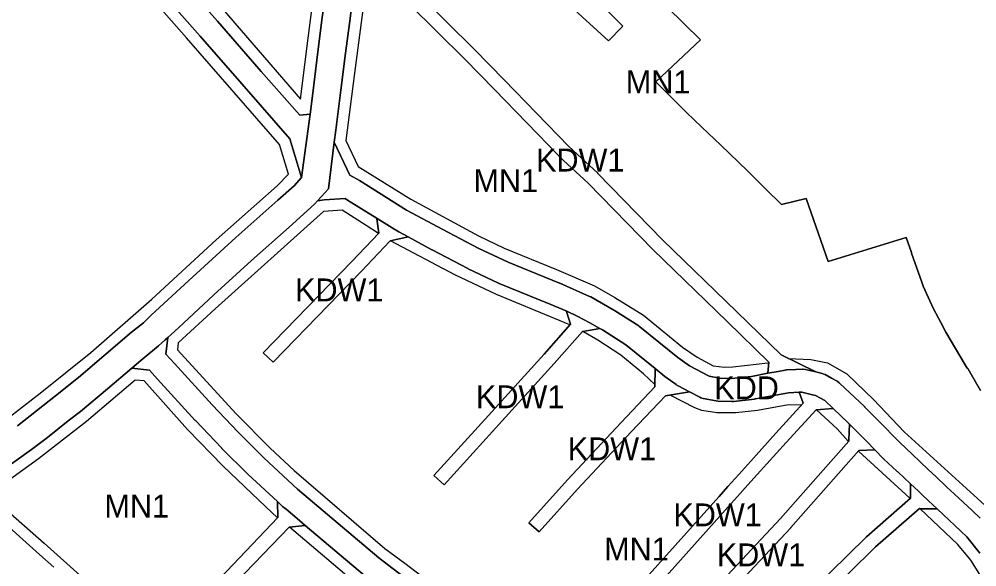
# Model space of a CAD drawing. Extents: x -284239 to -281592, y 34477 to 37267.
# Drawn here: x -283512.6 to -283094, y 35490.3 to 35729.6 of the extents above; entities that cross this region are included whole.
import ezdxf

# ---------------------------------------------------------------- set-up
doc = ezdxf.new("R2010")
doc.units = 0
for name, color, linetype in [('linie_rozgraniczajace', 7, 'Continuous'), ('linie_zabudowy_nieprzekraczalne', 7, 'Continuous'), ('oznaczenia_przeznaczen', 7, 'Continuous')]:
    doc.layers.add(name, color=color, linetype=linetype)

msp = doc.modelspace()

# ---------------------------------------------------------------- linework, layer by layer
at = {"layer": 'linie_rozgraniczajace'}
for points in [[(-283349.735, 35805.983), (-283349.502, 35806.716), (-283347.736, 35812.259), (-283345.668, 35818.639), (-283344.649, 35821.859), (-283344.561, 35822.155), (-283342.259, 35814.684), (-283340.653, 35813.099), (-283314.405, 35787.199), (-283293.67, 35766.75), (-283260.03, 35733.57), (-283258.538, 35733.588), (-283255.81, 35733.62), (-283248.69, 35726.59), (-283255.01, 35720.19), (-283271.48, 35735.12), (-283286.84, 35750.42), (-283304.28, 35767.69), (-283309.22, 35772.58), (-283343.987, 35807.004), (-283344.662, 35807.672)], [(-283405.892, 35583.865), (-283367.249, 35623.692), (-283355.369, 35636.167), (-283356.246, 35642.43), (-283356.174, 35642.531), (-283351.873, 35639.838), (-283348.414, 35637.671), (-283348.223, 35637.573), (-283348.144, 35637.513), (-283346.6, 35636.675), (-283342.497, 35634.45), (-283349.694, 35632.864), (-283350.526, 35632.552), (-283362.924, 35619.536), (-283362.94, 35619.513), (-283401.586, 35579.687)], [(-283331.293, 35530.227), (-283305.991, 35558.112), (-283283.18, 35583.183), (-283271.69, 35596.417), (-283273.302, 35601.939), (-283273.289, 35601.964), (-283268.654, 35599.915), (-283263.111, 35596.934), (-283258.791, 35594.465), (-283266.225, 35593.161), (-283266.426, 35593.161), (-283278.699, 35579.197), (-283278.724, 35579.164), (-283301.549, 35554.079), (-283326.849, 35526.195)], [(-283289.83, 35509.614), (-283272.958, 35528.334), (-283272.93, 35528.369), (-283249.481, 35553.42), (-283234.751, 35568.99), (-283234.584, 35576.912), (-283230.431, 35573.556), (-283225.502, 35570.036), (-283225.128, 35569.768), (-283224.555, 35569.415), (-283219.593, 35566.796), (-283230.165, 35565.107), (-283245.112, 35549.31), (-283268.53, 35524.289), (-283285.373, 35505.597)], [(-283261.298, 35460.15), (-283210.762, 35516.507), (-283206.679, 35521.057), (-283202.803, 35525.377), (-283198.107, 35530.61), (-283194.076, 35535.102), (-283181.848, 35548.728), (-283169.95, 35561.785), (-283171.609, 35566.589), (-283170.52, 35566.632), (-283166.417, 35565.662), (-283164.569, 35565.225), (-283162.307, 35563.981), (-283160.442, 35562.955), (-283156.878, 35559.563), (-283164.204, 35558.906), (-283177.398, 35544.705), (-283190.045, 35530.61), (-283194.076, 35526.119), (-283198.618, 35521.057), (-283202.803, 35516.393), (-283206.296, 35512.5), (-283256.831, 35456.145)], [(-283242.392, 35442.939), (-283213.619, 35475.417), (-283213.588, 35475.438), (-283213.562, 35475.479), (-283179.793, 35511.495), (-283161.166, 35532.63), (-283149.95, 35545.248), (-283149.998, 35545.727), (-283149.736, 35552.671), (-283149.639, 35552.65), (-283146.347, 35549.301), (-283144.476, 35547.397), (-283142.132, 35545.012), (-283138.586, 35541.406), (-283145.528, 35541.192), (-283156.673, 35528.655), (-283175.322, 35507.493), (-283175.356, 35507.469), (-283175.384, 35507.425), (-283209.156, 35471.406), (-283237.901, 35438.96)], [(-283221.889, 35418.595), (-283197.68, 35445.979), (-283197.655, 35445.997), (-283197.633, 35446.031), (-283166.082, 35480.096), (-283166.025, 35480.135), (-283165.984, 35480.197), (-283142.436, 35503.348), (-283142.351, 35503.404), (-283142.303, 35503.471), (-283123.015, 35520.27), (-283123.015, 35526.596), (-283119.508, 35523.325), (-283118.003, 35521.92), (-283115.117, 35519.192), (-283111.325, 35515.608), (-283118.634, 35515.726), (-283119.023, 35515.79), (-283138.294, 35499.006), (-283161.727, 35475.967), (-283193.208, 35441.979), (-283217.394, 35414.621)], [(-283459.881, 35455.783), (-283452.711, 35455.963), (-283399.464, 35511.822), (-283399.464, 35511.924), (-283399.734, 35518.856), (-283397.587, 35516.882), (-283397.44, 35516.75), (-283395.961, 35515.497), (-283391.099, 35511.382), (-283387.556, 35508.383), (-283394.625, 35507.71), (-283448.28, 35451.829), (-283448.198, 35444.961), (-283451.752, 35448.213), (-283456.211, 35452.291), (-283456.735, 35452.771)], [(-283448.28, 35451.829), (-283394.625, 35507.71), (-283387.556, 35508.383), (-283361.724, 35486.517), (-283361.651, 35486.472), (-283361.462, 35486.31), (-283335.431, 35466.436), (-283335.282, 35466.336), (-283335.195, 35466.214), (-283319.25, 35452.214), (-283318.647, 35444.882), (-283324.984, 35437.311), (-283356.337, 35432.416), (-283382.95, 35396.045), (-283383.06, 35396.036), (-283389.857, 35395.197), (-283396.132, 35400.193), (-283407.596, 35409.26), (-283420.363, 35420.255), (-283434.537, 35432.552), (-283440.842, 35438.232), (-283448.198, 35444.961)]]:
    msp.add_lwpolyline(points, close=True, dxfattribs=at)
for points in [[(-283445.477, 35750.899), (-283425.955, 35728.745), (-283406.767, 35706.816), (-283389.981, 35687.607), (-283385.372, 35688.169), (-283389.119, 35660.419), (-283394.259, 35677.377), (-283414.295, 35700.233), (-283433.469, 35722.148), (-283452.999, 35744.31)], [(-283377.998, 35745.258), (-283380.239, 35729.365), (-283382.48, 35711.7), (-283384.251, 35697.318), (-283385.372, 35688.169), (-283389.981, 35687.607), (-283406.767, 35706.816), (-283425.955, 35728.745), (-283445.477, 35750.899)], [(-283350.085, 35752.642), (-283313.572, 35716.394), (-283313.552, 35716.37), (-283300.572, 35703.128), (-283272.378, 35674.01), (-283259.737, 35662.291), (-283259.695, 35662.23), (-283259.629, 35662.185), (-283231.396, 35633.234), (-283198.892, 35601.751), (-283179.603, 35582.897), (-283164.461, 35575.475), (-283168.882, 35576.52), (-283170.032, 35576.654), (-283170.133, 35576.634), (-283170.224, 35576.65), (-283173.099, 35576.54), (-283177.104, 35576.386), (-283177.216, 35576.361), (-283177.833, 35576.304), (-283180.86, 35575.736), (-283185.361, 35574.892), (-283184.93, 35579.715), (-283203.076, 35597.451), (-283235.601, 35628.954), (-283235.626, 35628.99), (-283235.662, 35629.014), (-283263.872, 35657.943), (-283276.516, 35669.665), (-283276.562, 35669.731), (-283276.632, 35669.778), (-283304.87, 35698.942), (-283317.814, 35712.15), (-283354.266, 35748.338)], [(-283127.717, 35544.613), (-283137.344, 35554.407), (-283142.918, 35560.078), (-283142.99, 35560.126), (-283143.037, 35560.194), (-283154.017, 35570.646), (-283154.215, 35570.774), (-283155.055, 35571.405), (-283157.487, 35572.743), (-283160.346, 35574.315), (-283160.843, 35574.554), (-283161.606, 35574.8), (-283164.461, 35575.475), (-283179.603, 35582.897), (-283198.892, 35601.751), (-283231.396, 35633.234), (-283259.629, 35662.185), (-283259.695, 35662.23), (-283259.737, 35662.291), (-283272.378, 35674.01), (-283300.572, 35703.128), (-283313.552, 35716.37), (-283313.572, 35716.394), (-283350.085, 35752.642)], [(-283354.266, 35748.338), (-283317.814, 35712.15), (-283304.87, 35698.942), (-283276.632, 35669.778), (-283276.562, 35669.731), (-283276.516, 35669.665), (-283263.872, 35657.943), (-283235.662, 35629.014), (-283235.626, 35628.99), (-283235.601, 35628.954), (-283203.076, 35597.451), (-283184.93, 35579.715), (-283185.361, 35574.892), (-283192.474, 35573.558), (-283201.191, 35572.562), (-283206.465, 35572.736), (-283211.035, 35573.586), (-283219.589, 35578.101), (-283224.748, 35581.786), (-283241.365, 35595.25), (-283241.547, 35595.359), (-283241.825, 35595.581), (-283252.408, 35602.328), (-283252.544, 35602.399), (-283252.615, 35602.453), (-283262.802, 35608.274), (-283263.242, 35608.49), (-283263.273, 35608.512), (-283276.238, 35614.2), (-283276.308, 35614.215), (-283276.369, 35614.256), (-283298.931, 35623.399), (-283311.937, 35629.512), (-283327.42, 35637.646), (-283343.238, 35646.229), (-283363.898, 35659.169), (-283368.04, 35661.429), (-283374.932, 35675.891), (-283374.247, 35681.06), (-283372.006, 35698.621), (-283369.974, 35714.722), (-283368.254, 35727.698), (-283366.17, 35743.956)], [(-283366.17, 35743.956), (-283368.254, 35727.698), (-283369.974, 35714.722), (-283372.006, 35698.621), (-283374.247, 35681.06), (-283374.932, 35675.891), (-283377.459, 35655.416), (-283382.181, 35650.222), (-283383.47, 35648.805), (-283394.517, 35638.8), (-283410.983, 35624.209), (-283427.502, 35609.15), (-283442.978, 35594.82), (-283447.681, 35590.537), (-283448.815, 35589.505), (-283451.738, 35586.915), (-283459.357, 35580.433), (-283463.326, 35577.08), (-283474.035, 35568.036), (-283485.812, 35558.135), (-283491.231, 35554.07), (-283500.194, 35546.88), (-283507.177, 35541.564), (-283521.715, 35531.195)], [(-283513.325, 35551.986), (-283496.755, 35565.013), (-283486.594, 35573.09), (-283463.457, 35592.787), (-283458.298, 35596.904), (-283454.859, 35600.239), (-283438.393, 35615.455), (-283417.914, 35634.162), (-283399.519, 35650.472), (-283392.432, 35656.83), (-283389.119, 35660.419), (-283385.372, 35688.169), (-283384.251, 35697.318), (-283382.48, 35711.7), (-283380.239, 35729.365), (-283377.998, 35745.258)], [(-283452.999, 35744.31), (-283433.469, 35722.148), (-283414.295, 35700.233), (-283394.259, 35677.377), (-283389.119, 35660.419), (-283392.432, 35656.83), (-283399.519, 35650.472), (-283417.914, 35634.162), (-283438.393, 35615.455), (-283454.859, 35600.239), (-283458.298, 35596.904), (-283463.457, 35592.787), (-283486.594, 35573.09), (-283496.755, 35565.013), (-283513.325, 35551.986)], [(-283271.48, 35735.12), (-283255.01, 35720.19), (-283248.69, 35726.59), (-283255.81, 35733.62)], [(-283092.471, 35567.431), (-283098.027, 35576.957), (-283098.186, 35577.14), (-283099.081, 35578.638), (-283107.513, 35592.892), (-283109.739, 35597.087), (-283112.992, 35603.08), (-283114.619, 35606.59), (-283117.444, 35613.01), (-283118.043, 35614.722), (-283122.542, 35627.385), (-283122.524, 35627.651), (-283124.934, 35634.172), (-283158.969, 35623.797), (-283168.586, 35651.283), (-283179.46, 35648.69), (-283186.351, 35655.531), (-283194.268, 35663.39), (-283205.878, 35674.619), (-283214.194, 35682.475), (-283220.91, 35688.82), (-283228.949, 35696.828), (-283234.337, 35702.194), (-283214.743, 35720.578), (-283229.344, 35734.896)], [(-283229.344, 35734.896), (-283214.743, 35720.578), (-283234.337, 35702.194), (-283228.949, 35696.828), (-283220.91, 35688.82), (-283214.194, 35682.475), (-283205.878, 35674.619), (-283194.268, 35663.39), (-283186.351, 35655.531), (-283179.46, 35648.69), (-283168.586, 35651.283), (-283158.969, 35623.797), (-283124.934, 35634.172), (-283122.524, 35627.651), (-283122.542, 35627.385), (-283118.043, 35614.722), (-283117.444, 35613.01), (-283114.619, 35606.59), (-283112.992, 35603.08), (-283109.739, 35597.087), (-283107.513, 35592.892), (-283099.081, 35578.638), (-283098.186, 35577.14), (-283098.027, 35576.957), (-283092.471, 35567.431)], [(-283382.181, 35650.222), (-283377.459, 35655.416), (-283374.932, 35675.891), (-283368.04, 35661.429), (-283363.898, 35659.169), (-283343.238, 35646.229), (-283327.42, 35637.646), (-283311.937, 35629.512), (-283298.931, 35623.399), (-283276.369, 35614.256), (-283276.308, 35614.215), (-283276.238, 35614.2), (-283263.273, 35608.512), (-283263.242, 35608.49), (-283262.802, 35608.274), (-283252.615, 35602.453), (-283252.544, 35602.399), (-283252.408, 35602.328), (-283241.825, 35595.581), (-283241.547, 35595.359), (-283241.365, 35595.25), (-283224.748, 35581.786), (-283219.589, 35578.101), (-283211.035, 35573.586), (-283206.465, 35572.736), (-283201.191, 35572.562), (-283192.474, 35573.558), (-283185.361, 35574.892), (-283180.86, 35575.736), (-283177.833, 35576.304), (-283177.216, 35576.361), (-283177.104, 35576.386), (-283173.099, 35576.54), (-283170.224, 35576.65), (-283170.133, 35576.634), (-283170.032, 35576.654), (-283168.882, 35576.52), (-283164.461, 35575.475), (-283161.606, 35574.8), (-283160.843, 35574.554), (-283160.346, 35574.315), (-283157.487, 35572.743), (-283155.055, 35571.405), (-283154.215, 35570.774), (-283154.017, 35570.646), (-283143.037, 35560.194), (-283142.99, 35560.126), (-283142.918, 35560.078), (-283137.344, 35554.407), (-283127.717, 35544.613), (-283122.28, 35539.555), (-283115.266, 35532.893), (-283111.797, 35529.599), (-283107.559, 35525.573), (-283107.141, 35525.176), (-283103.955, 35522.213), (-283096.13, 35514.935), (-283092.56, 35511.615)], [(-283448.447, 35583.255), (-283447.681, 35590.537), (-283442.978, 35594.82), (-283427.502, 35609.15), (-283410.983, 35624.209), (-283394.517, 35638.8), (-283383.47, 35648.805), (-283382.181, 35650.222), (-283379.257, 35650.617), (-283370.159, 35651.232), (-283369.038, 35650.589), (-283356.174, 35642.531), (-283356.246, 35642.43), (-283355.369, 35636.167), (-283367.249, 35623.692), (-283405.892, 35583.865), (-283401.586, 35579.687), (-283362.94, 35619.513), (-283362.924, 35619.536), (-283350.526, 35632.552), (-283349.694, 35632.864), (-283342.497, 35634.45), (-283332.159, 35628.841), (-283332.107, 35628.814), (-283316.49, 35620.607), (-283316.315, 35620.526), (-283316.291, 35620.509), (-283303.062, 35614.291), (-283302.934, 35614.262), (-283302.813, 35614.182), (-283280.191, 35605.015), (-283273.289, 35601.964), (-283273.302, 35601.939), (-283271.69, 35596.417), (-283283.18, 35583.183), (-283305.991, 35558.112), (-283331.293, 35530.227), (-283326.849, 35526.195), (-283301.549, 35554.079), (-283278.724, 35579.164), (-283278.699, 35579.197), (-283266.426, 35593.161), (-283266.225, 35593.161), (-283258.791, 35594.465), (-283257.682, 35593.831), (-283247.44, 35587.302), (-283234.584, 35576.912), (-283234.751, 35568.99), (-283249.481, 35553.42), (-283272.93, 35528.369), (-283272.958, 35528.334), (-283289.83, 35509.614), (-283285.373, 35505.597), (-283268.53, 35524.289), (-283245.112, 35549.31), (-283230.165, 35565.107), (-283219.593, 35566.796), (-283215.03, 35564.388), (-283214.61, 35564.19), (-283213.611, 35563.894), (-283207.922, 35562.836), (-283207.273, 35562.776), (-283207.172, 35562.754), (-283201.153, 35562.556), (-283201.074, 35562.57), (-283200.989, 35562.553), (-283200.421, 35562.585), (-283191.16, 35563.643), (-283191.037, 35563.675), (-283190.807, 35563.697), (-283176.352, 35566.407), (-283171.609, 35566.589), (-283169.95, 35561.785), (-283181.848, 35548.728), (-283194.076, 35535.102), (-283198.107, 35530.61), (-283202.803, 35525.377), (-283206.679, 35521.057), (-283210.762, 35516.507), (-283261.298, 35460.15)], [(-283128.568, 35531.777), (-283128.874, 35532.045), (-283128.922, 35532.076), (-283134.61, 35537.367), (-283134.672, 35537.457), (-283134.77, 35537.523), (-283138.586, 35541.406), (-283142.132, 35545.012), (-283144.476, 35547.397), (-283146.347, 35549.301), (-283149.639, 35552.65), (-283149.992, 35553.008), (-283156.878, 35559.563), (-283160.442, 35562.955), (-283162.307, 35563.981), (-283164.569, 35565.225), (-283166.417, 35565.662), (-283170.52, 35566.632), (-283171.609, 35566.589), (-283176.352, 35566.407), (-283190.807, 35563.697), (-283191.037, 35563.675), (-283191.16, 35563.643), (-283200.421, 35562.585), (-283200.989, 35562.553), (-283201.074, 35562.57), (-283201.153, 35562.556), (-283207.172, 35562.754), (-283207.273, 35562.776), (-283207.922, 35562.836), (-283213.611, 35563.894), (-283214.61, 35564.19), (-283215.03, 35564.388), (-283219.593, 35566.796), (-283224.555, 35569.415), (-283225.128, 35569.768), (-283225.502, 35570.036), (-283230.431, 35573.556), (-283234.584, 35576.912), (-283247.44, 35587.302), (-283257.682, 35593.831), (-283258.791, 35594.465), (-283263.111, 35596.934), (-283268.654, 35599.915), (-283273.289, 35601.964), (-283280.191, 35605.015), (-283302.813, 35614.182), (-283302.934, 35614.262), (-283303.062, 35614.291), (-283316.291, 35620.509), (-283316.315, 35620.526), (-283316.49, 35620.607), (-283332.107, 35628.814), (-283332.159, 35628.841), (-283342.497, 35634.45), (-283346.6, 35636.675), (-283348.144, 35637.513), (-283348.223, 35637.573), (-283348.414, 35637.671), (-283351.873, 35639.838), (-283356.174, 35642.531), (-283369.038, 35650.589), (-283370.159, 35651.232), (-283379.257, 35650.617), (-283382.181, 35650.222)], [(-283463.326, 35577.08), (-283459.357, 35580.433), (-283451.738, 35586.915), (-283448.815, 35589.505), (-283447.681, 35590.537), (-283448.447, 35583.255), (-283444.713, 35579.101), (-283428.291, 35561.069), (-283416.851, 35549.094), (-283405.713, 35537.956), (-283390.9, 35524.315), (-283355.39, 35494.257), (-283328.475, 35473.622)], [(-283328.475, 35473.622), (-283355.39, 35494.257), (-283390.9, 35524.315), (-283405.713, 35537.956), (-283416.851, 35549.094), (-283428.291, 35561.069), (-283444.713, 35579.101), (-283448.447, 35583.255)], [(-283521.715, 35531.195), (-283507.177, 35541.564), (-283500.194, 35546.88), (-283491.231, 35554.07), (-283485.812, 35558.135), (-283474.035, 35568.036), (-283463.326, 35577.08), (-283455.628, 35576.284), (-283452.126, 35572.39), (-283435.644, 35554.291), (-283435.599, 35554.26), (-283435.563, 35554.204), (-283424.042, 35542.145), (-283423.996, 35542.113), (-283423.963, 35542.063), (-283412.711, 35530.812), (-283412.62, 35530.751), (-283412.563, 35530.67), (-283399.734, 35518.856), (-283399.464, 35511.924), (-283399.464, 35511.822), (-283452.711, 35455.963)], [(-283361.724, 35486.517), (-283387.556, 35508.383), (-283391.099, 35511.382), (-283395.961, 35515.497), (-283397.44, 35516.75), (-283397.587, 35516.882), (-283399.734, 35518.856), (-283412.563, 35530.67), (-283412.62, 35530.751), (-283412.711, 35530.812), (-283423.963, 35542.063), (-283423.996, 35542.113), (-283424.042, 35542.145), (-283435.563, 35554.204), (-283435.599, 35554.26), (-283435.644, 35554.291), (-283452.126, 35572.39), (-283455.628, 35576.284), (-283463.326, 35577.08)], [(-283256.831, 35456.145), (-283206.296, 35512.5), (-283202.803, 35516.393), (-283198.618, 35521.057), (-283194.076, 35526.119), (-283190.045, 35530.61), (-283177.398, 35544.705), (-283164.204, 35558.906), (-283156.878, 35559.563), (-283149.992, 35553.008), (-283149.639, 35552.65), (-283149.736, 35552.671), (-283149.998, 35545.727), (-283149.95, 35545.248), (-283161.166, 35532.63), (-283179.793, 35511.495), (-283213.562, 35475.479)], [(-283209.156, 35471.406), (-283175.384, 35507.425), (-283175.356, 35507.469), (-283175.322, 35507.493), (-283156.673, 35528.655), (-283145.528, 35541.192), (-283138.586, 35541.406), (-283134.77, 35537.523), (-283134.672, 35537.457), (-283134.61, 35537.367), (-283128.922, 35532.076), (-283128.874, 35532.045), (-283128.568, 35531.777), (-283123.015, 35526.596), (-283123.015, 35520.27), (-283142.303, 35503.471), (-283142.351, 35503.404), (-283142.436, 35503.348), (-283165.984, 35480.197)], [(-283092.56, 35511.615), (-283096.13, 35514.935), (-283103.955, 35522.213), (-283107.141, 35525.176), (-283107.559, 35525.573), (-283111.797, 35529.599), (-283115.266, 35532.893), (-283122.28, 35539.555), (-283127.717, 35544.613)], [(-283092.708, 35496.233), (-283098.436, 35503.424), (-283111.325, 35515.608), (-283115.117, 35519.192), (-283118.003, 35521.92), (-283119.508, 35523.325), (-283123.015, 35526.596), (-283128.568, 35531.777)], [(-283524.385, 35514.239), (-283503.633, 35495.708), (-283497.484, 35490.185)], [(-283497.484, 35490.185), (-283503.633, 35495.708), (-283524.385, 35514.239)], [(-283161.727, 35475.967), (-283138.294, 35499.006), (-283119.023, 35515.79), (-283118.634, 35515.726), (-283111.325, 35515.608), (-283098.436, 35503.424), (-283092.708, 35496.233)]]:
    msp.add_lwpolyline(points, dxfattribs=at)
at = {"layer": 'linie_zabudowy_nieprzekraczalne'}
for points in [[(-283496.86, 35817.549), (-283493.494, 35813.784), (-283459.495, 35774.758), (-283423.908, 35734.343), (-283389.645, 35694.655), (-283386.205, 35721.312), (-283383.295, 35744.066), (-283382.501, 35752.004), (-283378.664, 35767.548), (-283373.108, 35788.318), (-283366.229, 35810.212), (-283358.159, 35835.744), (-283347.585, 35872.161)], [(-283394.804, 35661.847), (-283398.773, 35674.877), (-283439.519, 35721.51), (-283481.058, 35768.805)], [(-283359.888, 35752.701), (-283366.097, 35706.098), (-283369.801, 35676.597), (-283364.377, 35665.22), (-283341.358, 35650.999), (-283311.857, 35634.991), (-283300.612, 35629.633), (-283277.726, 35620.241), (-283261.189, 35613.097), (-283252.193, 35607.938), (-283239.758, 35600.265), (-283222.692, 35586.374), (-283216.21, 35581.876), (-283209.331, 35578.172), (-283204.304, 35577.51), (-283200.599, 35577.643), (-283185.395, 35579.399)], [(-283591.125, 35740.362), (-283640.338, 35695.581), (-283690.873, 35650.932), (-283690.873, 35648.154), (-283655.154, 35607.739), (-283618.51, 35566.001), (-283585.701, 35528.166), (-283580.806, 35526.578), (-283569.032, 35529.489), (-283555.803, 35533.127), (-283534.901, 35542.519), (-283516.909, 35555.748), (-283503.416, 35566.133), (-283481.323, 35583.993), (-283454.6, 35607.21), (-283426.422, 35633.139), (-283399.831, 35656.819), (-283394.804, 35661.847)], [(-283355.523, 35636.02), (-283360.937, 35639.423), (-283371.388, 35646.17), (-283379.59, 35645.641), (-283426.951, 35603.109), (-283443.091, 35588.16), (-283443.355, 35585.117), (-283417.823, 35557.336), (-283402.874, 35542.122), (-283392.423, 35532.399), (-283352.735, 35498.4), (-283344.004, 35491.984), (-283327.335, 35479.151), (-283299.157, 35454.611), (-283245.579, 35410.492), (-283216.21, 35386.018), (-283206.553, 35377.022), (-283183.798, 35353.077), (-283170.437, 35336.871), (-283167.923, 35336.739), (-283147.683, 35355.921), (-283124.399, 35374.905), (-283078.759, 35414.527), (-283054.285, 35435.561)], [(-283271.914, 35596.068), (-283303.919, 35609.261), (-283322.176, 35617.86), (-283350.231, 35632.712)], [(-283234.74, 35570.006), (-283239.758, 35574.666), (-283249.68, 35582.736), (-283259.611, 35589.321), (-283266.226, 35593.157)], [(-283176.532, 35581.383), (-283166.61, 35580.986), (-283159.324, 35579.495), (-283150.858, 35574.6), (-283139.216, 35563.488), (-283125.722, 35549.332), (-283088.903, 35515.874), (-283087.093, 35513.844)], [(-283399.708, 35511.798), (-283404.726, 35516.59), (-283423.379, 35534.317), (-283438.989, 35550.391), (-283457.907, 35571.557), (-283461.876, 35571.822), (-283483.175, 35553.896), (-283504.077, 35537.492), (-283522.201, 35524.528), (-283519.952, 35516.855), (-283501.696, 35500.715), (-283467.565, 35470.023), (-283453.022, 35455.97)], [(-283170.711, 35561.01), (-283176.4, 35561.142), (-283189.884, 35558.659), (-283199.409, 35557.601), (-283207.611, 35557.601), (-283214.225, 35558.659), (-283217.268, 35559.85), (-283228.126, 35565.376)], [(-283150.206, 35545.267), (-283155.091, 35550.655), (-283164.096, 35558.893)], [(-283123.351, 35520.264), (-283145.708, 35540.902)], [(-283085.515, 35475.682), (-283096.618, 35493.174), (-283102.306, 35500.054), (-283118.853, 35515.634)], [(-283318.644, 35444.885), (-283336.86, 35461.16), (-283363.715, 35481.533), (-283394.417, 35507.696)]]:
    msp.add_lwpolyline(points, dxfattribs=at)

# ---------------------------------------------------------------- texts
at = {"layer": 'oznaczenia_przeznaczen'}
for s, p in [('MN1', (-283247.466, 35697.194)), ('KDW1', (-283286.671, 35663.06)), ('MN1', (-283314.023, 35654.07)), ('KDW1', (-283392.01, 35606.325)), ('KDD', (-283208.783, 35563.537)), ('KDW1', (-283312.947, 35559.634)), ('KDW1', (-283272.827, 35536.897)), ('MN1', (-283475.321, 35511.872)), ('KDW1', (-283226.666, 35508.026)), ('MN1', (-283256.923, 35493.103)), ('KDW1', (-283207.67, 35490.562))]:
    msp.add_text(s, height=10, dxfattribs=at).set_placement(p)

doc.saveas('drawing.dxf')
